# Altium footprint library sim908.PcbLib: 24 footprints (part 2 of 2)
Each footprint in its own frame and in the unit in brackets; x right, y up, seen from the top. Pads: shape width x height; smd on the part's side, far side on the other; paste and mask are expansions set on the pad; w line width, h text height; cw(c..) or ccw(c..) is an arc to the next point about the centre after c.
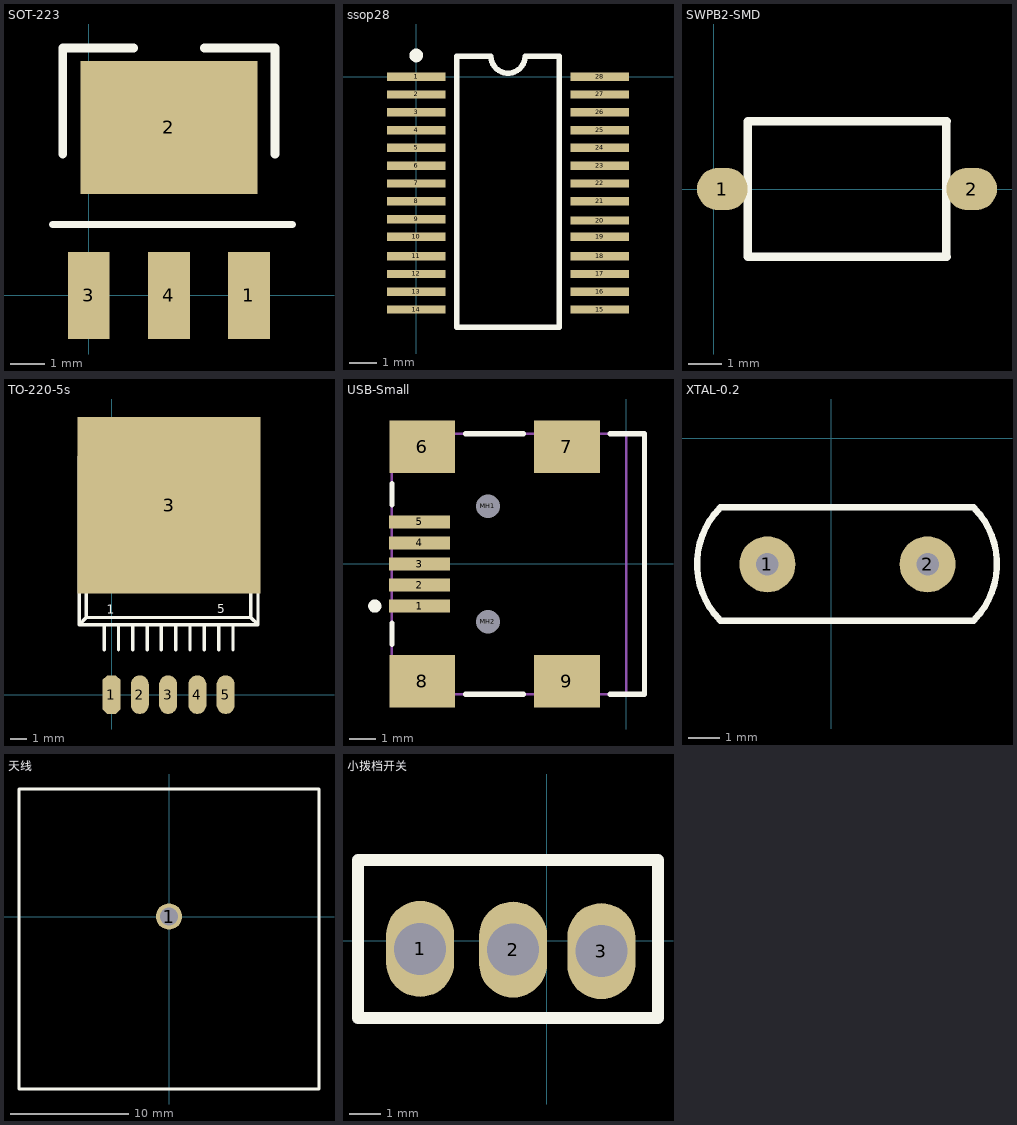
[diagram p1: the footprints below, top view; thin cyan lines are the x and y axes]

## SOT-223 [mm]
height 8.2
pads (4):
  rect 1.2x2.5 smd: 1(4.6,-0.011) 3(0,-0.011) 4(2.3,-0.011)
  rect 5.08x3.81 smd: 2(2.3,4.815)
Top Overlay:
  lines w0.2: -1.044,2.021 5.856,2.021
  lines w0.254: -0.748,4.053 -0.748,7.101 1.284,7.101 ; 3.316,7.101 5.348,7.101 5.348,4.053

## ssop28 [mm]
height 1.6
pads (28):
  rect 2.15x0.305 smd: 1(0,0) 2(0,-0.65) 3(0,-1.3) 4(0,-1.95) 5(0,-2.6) 6(0,-3.25) 7(0,-3.9) 8(0,-4.55) 9(0,-5.2) 10(0,-5.85) 11(0,-6.552) 12(0,-7.202) 13(0,-7.852) 14(0,-8.502) 15(6.7,-8.502) 16(6.7,-7.852) 17(6.7,-7.202) 18(6.7,-6.552) 19(6.7,-5.85) 20(6.7,-5.252) 21(6.7,-4.55) 22(6.7,-3.9) 23(6.7,-3.25) 24(6.7,-2.6) 25(6.7,-1.95) 26(6.7,-1.3) 27(6.7,-0.65) 28(6.7,0)
Top Overlay:
  circle w0.25: c0,0.775 r0.125
  lines w0.2: 1.475,-9.144 5.225,-9.144 5.225,0.75 3.975,0.75 cw(c3.35,0.75) 2.725,0.75 1.475,0.75 1.475,-9.144

## SWPB2-SMD [mil]
height 322.83
pads (2):
  oval 60x50 smd: 1(10,0) 2(305,0)
Top Overlay:
  lines w10: 275,-80 275,80 ; 275.59,-80 40,-80 40,80 275.59,80

## TO-220-5s [mil]
height 322.83
pads (6):
  oct 42x90 smd: 1(-0.33,0.19)
  oval 42x90 smd: 2(65.67,0.19) 3(131.67,0.19) 4(199.67,0.19) 5(265.67,0.19)
  rect 425x410 smd: 3(133.67,441.19)
Top Overlay:
  lines w7.87: -17.33,105.11 -17.33,163.19 ; 16,105.11 16,163.19 ; 49.34,105.11 49.34,163.19 ; 82.67,105.11 82.67,163.19 ; 116,105.11 116,163.19 ; 149.33,105.11 149.33,163.19 ; 182.67,105.11 182.67,163.19 ; 216,105.11 216,163.19 ; 249.33,105.11 249.33,163.19 ; 282.67,105.11 282.67,163.19 ; -75.66,163.19 341,163.19 ; -75.66,163.19 -75.66,504.85 ; -75.66,163.19 -59,179.85 ; -75.66,504.85 341,504.85 ; -75.66,504.85 -75.66,554.85 -17.33,571.52 282.67,571.52 341,554.85 341,504.85 ; -75.66,504.85 -59,488.19 ; -59,179.85 -59,488.19 ; -59,179.85 324.33,179.85 ; -59,488.19 324.33,488.19 ; 324.33,179.85 324.33,488.19 ; 324.33,179.85 341,163.19 ; 324.33,488.19 341,504.85 ; 341,163.19 341,504.85
  text "1" at -11.76,188.99 h20
  text "5" at 246.43,190.08 h20

## USB-Small [mm] "Connector; USB2.0, Type B, SM; 5 Position; Right Angle"
height 3.9
pads (11):
  rect 2.3x0.5 smd: 1(-7.85,-1.6) 2(-7.85,-0.8) 3(-7.85,0) 4(-7.85,0.8) 5(-7.85,1.6)
  rect 2.5x2 smd: 6(-7.75,4.45) 7(-2.25,4.45) 8(-7.75,-4.45) 9(-2.25,-4.45)
  round 0.6 hole 0.9 unplated: MH1(-5.25,2.2) MH2(-5.25,-2.2)
Top Overlay:
  circle w0.25: c-9.55,-1.6 r0.125
  lines w0.2: -8.9,-3.05 -8.9,-2.25 ; -8.9,2.25 -8.9,3.05 ; -6.1,-4.95 -3.9,-4.95 ; -6.1,4.95 -3.9,4.95 ; -0.6,-4.95 0.7,-4.95 0.7,4.95 -0.6,4.95
Mechanical 1:
  lines w0.1: 0,-4.95 0,4.95
Mechanical 13:
  lines w0.1: -8.9,-4.95 -8.9,4.95 0.7,4.95 0.7,-4.95 -8.9,-4.95
3D body: height 3.9, standoff 0, extent -8.9,-4.95 0.7,4.95

## XTAL-0.2 [mil]
height 149.61
pads (2):
  round 70 hole 28: 1(-79.92,-157.48) 2(120.08,-157.48)
Top Overlay:
  lines w8: 177.41,-227.79 -138.63,-227.79 cw(c-67.92,-157.08) -138.63,-86.37 177.41,-86.37 ; 177.48,-227.72 ccw(c106.77,-157.01) 177.48,-86.3

## 天线 [mm]
height 8.2
pads (1):
  round 2.2 hole 1.5: 1(0,0)
Top Overlay:
  lines w0.254: -12.7,-10.16 -12.7,-3.175 -12.7,10.16 -12.7,10.795 12.7,10.795 12.7,-13.97 12.7,-14.478 12.7,-14.605 -12.7,-14.605 -12.7,-10.033

## 小拨档开关 [mil]
height 322.83
pads (3):
  oval 85x120 hole 65: 1(-158.47,-9.84) 2(-42.32,-10.83) 3(67.91,-12.79)
Top Overlay:
  lines w15: -236.22,-96.46 138.78,-96.46 ; -236.22,-96.46 -236.22,-96.46 ; -236.22,-96.46 -236.22,101.38 ; -236.22,-96.46 -236.22,-96.46 ; -236.22,101.38 138.78,101.38 ; -236.22,101.38 -236.22,101.38 ; 138.78,-96.46 138.78,-96.46 ; 138.78,-96.46 138.78,101.38 ; 138.78,101.38 138.78,101.38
